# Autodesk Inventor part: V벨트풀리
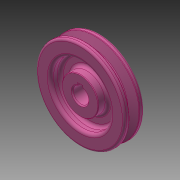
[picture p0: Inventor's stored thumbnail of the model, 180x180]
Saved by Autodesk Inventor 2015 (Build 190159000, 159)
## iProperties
Created: 2018-11
Part Number: V벨트풀리
Material: 알루미늄 6061
Document SubType Name: Modeling
Designer: mduedu
Density: 1 g/cm^3
Appearance: 분홍색
Author: mduedu
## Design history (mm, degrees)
sketch "스케치1"
  geometry: L1 (-9.5, 0)-(9.5, 0); L2 (9.5, 0)-(9.5, 42.7); L3 (9.5, 42.7)-(4.877, 42.7); L4 (-9.5, 42.7)-(-9.5, 0); L5 (-4.877, 42.7)-(-1.953, 33.7); L6 (-1.953, 33.7)-(1.953, 33.7); L7 (1.953, 33.7)-(4.877, 42.7); L8 (0, 0)-(0, 42.7); L9 (-9.5, 40)-(9.5, 40); L10 (-4.877, 42.7)-(-9.5, 42.7); L11 (4.877, 42.7)-(-4.877, 42.7); 3 further points
  constraints: 22 end point, 6 point on line, 4 parallel, 3 perpendicular, 2 midpoint, 1 coincident, 1 horizontal, 1 vertical, 1 other
  dimensions: "d2" = 19 distance of L2.end L4.start; "d3" = 80 diameter of L9 L1; "d4" = 36 deg angle of L7 L5; "d5" = 6.3 distance between parallel lines of L6 L9; "d6" = 8 distance of point (4, 40) point (-4, 40); "d27" = 2.7 distance between parallel lines of L3 L9
revolve "회전1" sketch "스케치1" stored, may be unused: angle "d7" = 90 deg
sketch "스케치2"
  geometry: L1 (-2.5, 7.071)-(2.5, 7.071); L2 (2.5, 7.071)-(2.5, 9.8); L3 (2.5, 9.8)-(-2.5, 9.8); L4 (-2.5, 9.8)-(-2.5, 7.071); A1 r 7.5 centre (0, 0) between (-2.5, 7.071) and (2.5, 7.071); 1 further point
  constraints: 8 end point, 2 parallel, 2 point on circle, 1 centre point, 1 coincident, 1 horizontal, 1 perpendicular
  dimensions: "d8" = 15 diameter of A1; "d10" = 17.3 dimension on A1 L3; "d11" = 5 distance of L2.end L3.end
extrude "돌출1" cut sketch "스케치2" stored distance "d12" = 10; taper "d13" = 0 deg
chamfer "모따기1" distance "d14" = 1; stored, may be unused: second distance "d15" = 2, angle "d16" = 45 deg
fillet "모깎기1" dims "d17" = 1, "d18" = 0.5, "d19" = 2
sketch "스케치3"
  geometry: C1 r 17.5 at (0, 0); C2 r 28.5 at (0, 0); 1 further point
  constraints: 2 centre point, 2 coincident
  dimensions: "d20" = 35 diameter of C1; "d23" = 57 diameter of C2
extrude "돌출2" cut sketch "스케치3" distance "d24" = 9.5; taper "d25" = 0 deg
fillet "모깎기2" dims "d26" = 3
chamfer "모따기2" distance "d28" = 0.5; stored, may be unused: second distance "d29" = 2, angle "d30" = 45 deg
node "솔리드1"
